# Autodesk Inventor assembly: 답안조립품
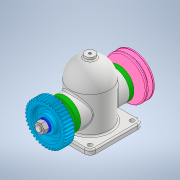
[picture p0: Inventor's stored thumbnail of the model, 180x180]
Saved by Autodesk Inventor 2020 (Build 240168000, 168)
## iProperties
Created: 2021-07
Part Number: 답안조립품
Document SubType Name: Assembly
Designer: Owner
Author: Owner
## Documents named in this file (14)
- C:\Users\Owner\Desktop\710716V1003\답안조립품.iam
- C:\Users\Owner\Desktop\710716V1003\본체.ipt
- C:\Users\Owner\Desktop\710716V1003\축.ipt
- C:\Users\Owner\Desktop\710716V1003\커버.ipt
- C:\Users\Owner\Desktop\710716V1003\와셔 12x24.ipt
- C:\Users\Owner\Desktop\710716V1003\스퍼기어.ipt
- C:\Users\Owner\Desktop\710716V1003\V-벨트풀리.ipt
- V-벨트풀리.ipt
- C:\Users\Owner\Desktop\710716V1003\볼트 M4.ipt
- C:\Users\Owner\Desktop\710716V1003\키 5x5x12.ipt
- C:\Users\Owner\Desktop\710716V1003\오일 실 26 38 8.ipt
- C:\Users\Owner\Desktop\710716V1003\부시.ipt
- C:\Users\Owner\Desktop\710716V1003\베어링 6203.ipt
- C:\Users\Owner\Desktop\710716V1003\너트 M12x1.25.ipt
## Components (1 placed, 1 different names)
1. V-벨트풀리:1
